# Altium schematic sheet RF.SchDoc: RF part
size A4; Author: PhA; SheetNumber: 4; SheetTotal: 8
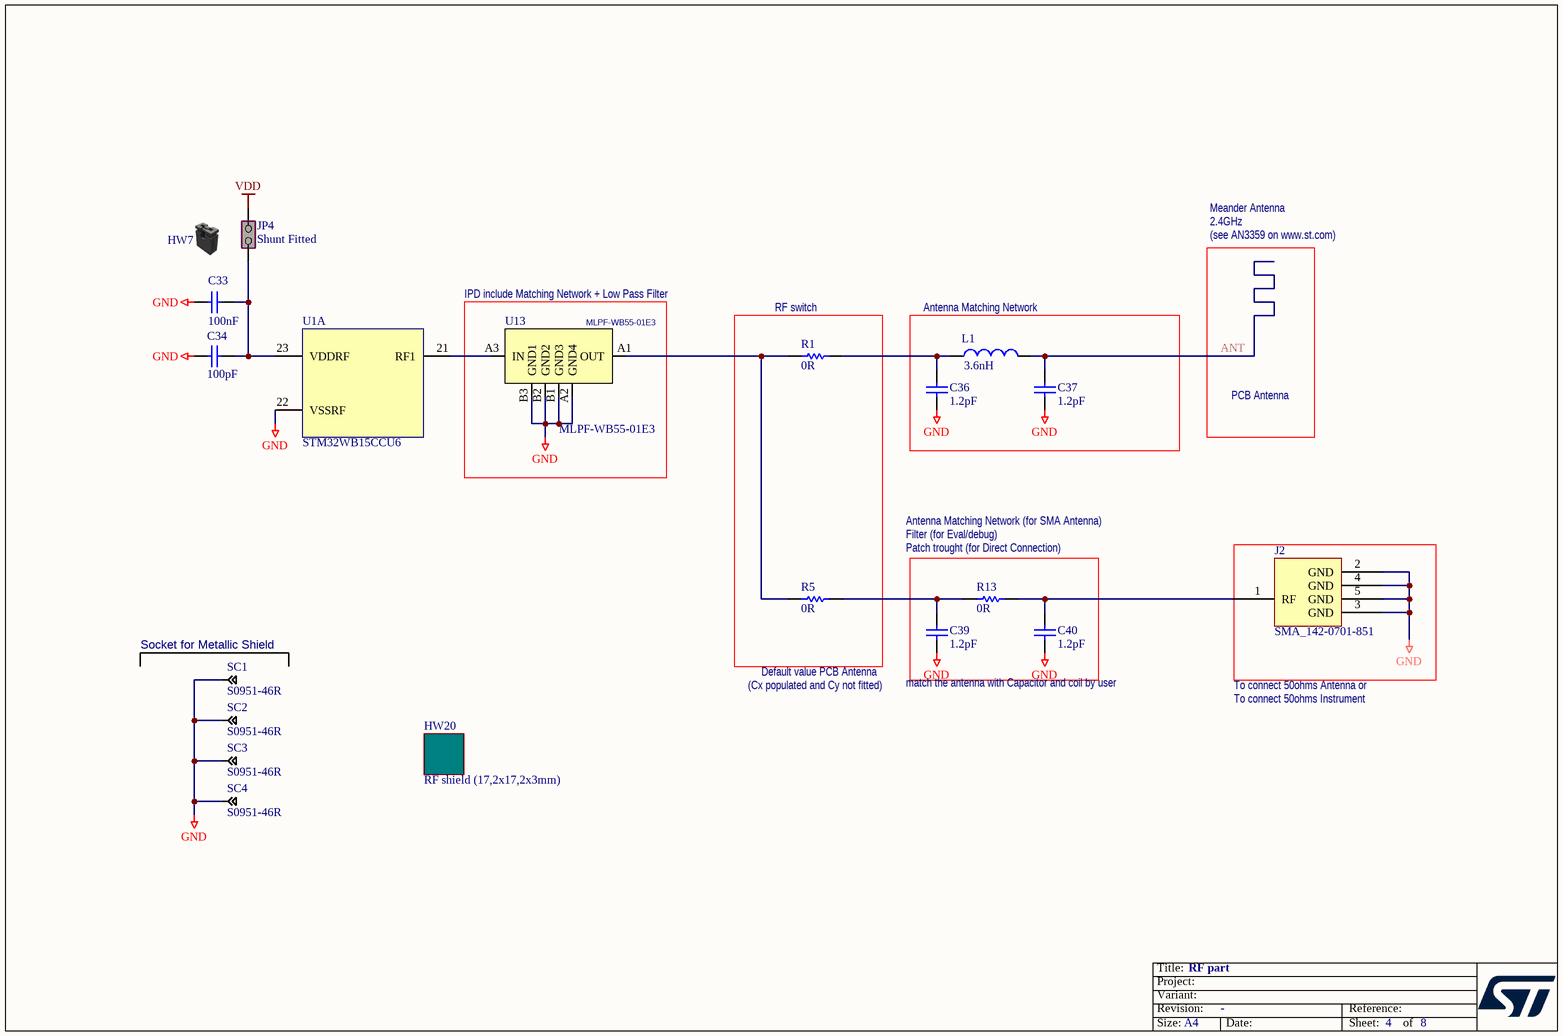
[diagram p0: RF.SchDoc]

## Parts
C33  value 100nF  [C0402]  (hidden comment: Capacitor)
C34  value 100pF  [C0402]  (hidden comment: Capacitor)
C36  value 1.2pF  [C0402]  (hidden comment: Capacitor)
C37  value 1.2pF  [C0402]  (hidden comment: Capacitor)
C39  value 1.2pF  [C0402]  (hidden comment: Capacitor)
C40  value 1.2pF  [C0402]  (hidden comment: Capacitor)
HW7  Shunt Black 2.54mm  (value not drawn)  (mechanical)
HW20  value RF shield (17,2x17,2x3mm)  [SHIELD_RF_ST-CUSTOM_17P2X17P2_H3]  (hidden comment: Daughter_Board)
J2  value SMA_142-0701-851  [CON_SMA-RF_CINCH_142-0701-851]  (hidden comment: SMA-J-P-H-ST-EM1)
JP4  value Shunt Fitted  [CON_SAMTEC_TSW-102-07-G-S]  (hidden comment: Jumper_Header 2x1 Fitted)
L1  value 3.6nH  [IND_0402_MURATA_LGQ15HS02_H0P5]  (hidden comment: Inductor)
R1  value 0R  [R0402]  (hidden comment: Resistor)
R5  value 0R  [R0402]  (hidden comment: Resistor)
R13  value 0R  [R0402]  (hidden comment: Resistor)
SC1  value S0951-46R  [CLIP_HARWIN_S0951-46R]  (hidden comment: Shield-clip_S0951-46R)
SC2  value S0951-46R  [CLIP_HARWIN_S0951-46R]  (hidden comment: Shield-clip_S0951-46R)
SC3  value S0951-46R  [CLIP_HARWIN_S0951-46R]  (hidden comment: Shield-clip_S0951-46R)
SC4  value S0951-46R  [CLIP_HARWIN_S0951-46R]  (hidden comment: Shield-clip_S0951-46R)
U1  value STM32WB15CCU6  [ICC_UFQFPN48-EPAD_7X7_H0P55_P050]  (hidden comment: STM32WB15_QFN48)  (part A of 5)
U13  MLPF-WB55-01E3  [ICC_BUMPLESS-CSP6_AN2348-FLIP-CHIP_1X1P60_P050-P0587]

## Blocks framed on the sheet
IPD include Matching Network + Low Pass Filter: U13
RF switch: R1 R5
Antenna Matching Network: C36 C37 L1

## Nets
GND: C33.1 C34.1 C36.1 C37.1 C39.1 C40.1 J2.2(GND) J2.3(GND) J2.4(GND) J2.5(GND) SC1.1 SC2.1 SC3.1 SC4.1 U1.22(VSSRF) U13.A2(GND4) U13.B1(GND3) U13.B2(GND2) U13.B3(GND1)
VDD: JP4.1(COMMON)
ANT: C37.2 L1.2
NetC33_2: C33.2 C34.2 JP4.2(NO) U1.23(VDDRF)
NetC36_2: C36.2 L1.1 R1.2
NetC39_2: C39.2 R5.2 R13.1
NetC40_2: C40.2 J2.1(RF) R13.2
NetR1_1: R1.1 R5.1 U13.A1(OUT)
NetU1_21: U1.21(RF1) U13.A3(IN)

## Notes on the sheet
- Meander Antenna
- 2.4GHz
- (see AN3359 on www.st.com)
- PCB Antenna
- Antenna Matching Network (for SMA Antenna)
- Filter (for Eval/debug)
- (near R13) Patch trought (for Direct Connection)
- (near SC1) Socket for Metallic Shield
- (near C39) (Cx populated and Cy not fitted)
- (near C39) Default value PCB Antenna
- match the antenna with Capacitor and coil by user
- To connect 50ohms Antenna or
- To connect 50ohms Instrument

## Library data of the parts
C33 = MCD-00006: Capacitor, MLCC, 100nF, 16V, X7R, +/-10%, 0402, T=0.5mm; Manufacturer_Part_Number: CC0402KRX7R7BB104; Manufacturer: YAGEO; Alternate_Manufacturer_Part_Number: GCM155R71C104KA55D; Alternate_Manufacturer: MURATA; Part_Preference: Recommended; Order_Code_RS: 616-9701
C34 = MCD-00205: Capacitor,MLCC,100pF,50V,NPO,+/-5%,0402,T=0,5mm; Manufacturer_Part_Number: CC0402JRNPO9BN101; Manufacturer: YAGEO; Part_Preference: Recommended
C36 C37 C39 C40 = MCD-02065: Capacitor, High Q type for high frequency and high power, SMD, 1.2pF, 50V, 0,05pf, 0402; Manufacturer_Part_Number: GJM1555C1H1R2WB01D; Manufacturer: MURATA; Part_Preference: Recommended; Order_Code_RS: 846-7246
HW7 = MCD-00043: SHUNT 2.54mm BLACK; Manufacturer_Part_Number: SNT-100-BK-G; Manufacturer: SAMTEC; Part_Type: Misc; Part_Preference: Recommended; Alternate_Manufacturer: JIUBABA; Alternate_Manufacturer_Part_Number: 316102S111A; Value: SNT-100-BK-G
HW20 = MCD-02088: RF shield (17,2x17,2x3mm), Brass with Sn finishing, Sheet tickness : 0,2mm; Part_Type: Misc; Part_Preference: Recommended
J2 = MCD-02072: RF SMA connector PCB edge; Manufacturer_Part_Number: 142-0701-851; Manufacturer: JOHNSON; Part_Preference: Recommended; Order_Code_RS: 885-7532
JP4 = MCD-00683: Header, 2x1, 2,54mm, VR, TH, Height 5.84mm/2.54mm - Shunt Fitted by default; Part_Type: Connector; Manufacturer_Part_Number: TSW-102-07-G-S; Manufacturer: SAMTEC; Alternate_Manufacturer_Part_Number: 313102S111116; Alternate_Manufacturer: LIANYI; Part_Preference: Recommended
L1 = MCD-01461: Inductor, LQG15H, 3.6nH, +-0.3nH 0402; Manufacturer_Part_Number: LQG15HS3N6S02; Manufacturer: MURATA; Part_Preference: Recommended
R1 R5 R13 = MCD-00052: Resistor,0R,0402,5%,1/16W; Part_Preference: Recommended; Manufacturer: YAGEO; Manufacturer_Part_Number: RC0402JR-070RL; Order_Code_RS: 618-5804
SC1-SC4 = MCD-01587: shield clip Harwin S0951-46R to fix RF shielded cavity; Part_Type: Misc; Part_Preference: Recommended
U1 = MCD-02058: Multiprotocol wireless 32-bit MCU ARM®-based Cortex®-M4 with FPU, Bluetooth® Low-Energy and 802.15.4 radio solution; Part_Type: IC; Manufacturer: STMICROELECTRONICS; Part_Preference: Recommended; Manufacturer_HQ_COO: EU; Component_Country_Of_Origin: China
U13 = MCD-02059: 2.4 GHz low pass filter matched to STM32WBx5Cx/Rx; Part_Type: IC; Manufacturer: STMICROELECTRONICS; Part_Preference: Recommended; Manufacturer_HQ_COO: EU; Component_Country_Of_Origin: China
